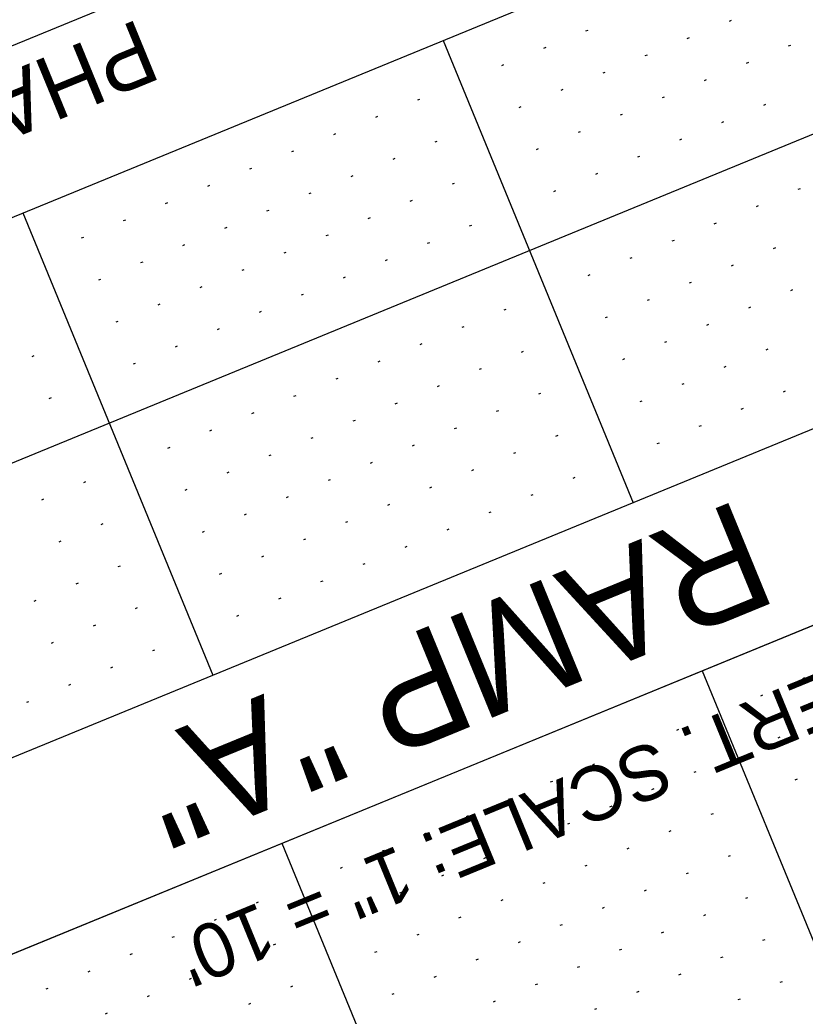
# Model space of a CAD drawing. Extents: x 2148770 to 2150891, y 142633 to 144465.
# Drawn here: x 2148940.4 to 2149026.8, y 143588.8 to 143698.4 of the extents above; entities that cross this region are included whole.
import ezdxf

# ---------------------------------------------------------------- set-up
doc = ezdxf.new("R2010")
doc.units = 0
for name, color, linetype in [('PR_Storm_Junction_Box', 7, 'Continuous'), ('SHT_Plan_Profile_Sheet_Txt', 7, 'Continuous'), ('SHT_Profile_Grid_Major', 7, 'Continuous'), ('SHT_Profile_Grid_Minor', 7, 'Continuous'), ('SHT_Scale', 7, 'Continuous'), ('SHT_Sheet_Border', 7, 'Continuous')]:
    doc.layers.add(name, color=color, linetype=linetype)

msp = doc.modelspace()

# ---------------------------------------------------------------- linework, layer by layer
at = {"layer": 'SHT_Profile_Grid_Major'}
for p, q in [((2150326.3, 144218.99), (2148869.31, 143620.81)), ((2150345.29, 144172.74), (2148888.3, 143574.55)), ((2148987.01, 143696.16), (2149007.9, 143645.28)), ((2148940.76, 143677.17), (2148961.65, 143626.29)), ((2149015.5, 143626.78), (2149167.42, 143256.75)), ((2148969.25, 143607.79), (2149121.17, 143237.76))]:
    msp.add_line(p, q, dxfattribs=at)
at = {"layer": 'SHT_Profile_Grid_Minor'}
for p, q in [((2149018.68, 143698.35), (2149018.45, 143698.25)), ((2149002.91, 143697.27), (2149002.67, 143697.18)), ((2149014.05, 143696.45), (2149013.82, 143696.35)), ((2148998.28, 143695.38), (2148998.05, 143695.28)), ((2149025.2, 143695.62), (2149024.97, 143695.53)), ((2149009.43, 143694.55), (2149009.2, 143694.45)), ((2148993.65, 143693.48), (2148993.42, 143693.38)), ((2149020.58, 143693.72), (2149020.35, 143693.63)), ((2149004.8, 143692.65), (2149004.57, 143692.55)), ((2149015.95, 143691.82), (2149015.72, 143691.73)), ((2149000.18, 143690.75), (2148999.95, 143690.66)), ((2149011.33, 143689.92), (2149011.1, 143689.83)), ((2148984.4, 143689.68), (2148984.17, 143689.58)), ((2148995.55, 143688.85), (2148995.32, 143688.76)), ((2149022.48, 143689.1), (2149022.25, 143689)), ((2148979.78, 143687.78), (2148979.55, 143687.68)), ((2149006.7, 143688.02), (2149006.47, 143687.93)), ((2149017.85, 143687.2), (2149017.62, 143687.1)), ((2148975.15, 143685.88), (2148974.92, 143685.79)), ((2149002.08, 143686.12), (2149001.85, 143686.03)), ((2148986.3, 143685.05), (2148986.07, 143684.96)), ((2149013.23, 143685.3), (2149013, 143685.2)), ((2148970.53, 143683.98), (2148970.3, 143683.89)), ((2148981.68, 143683.15), (2148981.45, 143683.06)), ((2148997.45, 143684.23), (2148997.22, 143684.13)), ((2149008.6, 143683.4), (2149008.37, 143683.3)), ((2148965.9, 143682.08), (2148965.67, 143681.99)), ((2148977.05, 143681.26), (2148976.82, 143681.16)), ((2149003.98, 143681.5), (2149003.75, 143681.4)), ((2148961.28, 143680.18), (2148961.05, 143680.09)), ((2148988.2, 143680.43), (2148987.97, 143680.33)), ((2148972.43, 143679.36), (2148972.2, 143679.26)), ((2148999.35, 143679.6), (2148999.12, 143679.51)), ((2149026.28, 143679.84), (2149026.04, 143679.75)), ((2148956.65, 143678.28), (2148956.42, 143678.19)), ((2148983.58, 143678.53), (2148983.34, 143678.43)), ((2149021.65, 143677.95), (2149021.42, 143677.85)), ((2148967.8, 143677.46), (2148967.57, 143677.36)), ((2148978.95, 143676.63), (2148978.72, 143676.53)), ((2148952.03, 143676.39), (2148951.79, 143676.29)), ((2148963.18, 143675.56), (2148962.94, 143675.46)), ((2148990.1, 143675.8), (2148989.87, 143675.71)), ((2149017.03, 143676.05), (2149016.79, 143675.95)), ((2148947.4, 143674.49), (2148947.17, 143674.39)), ((2148974.33, 143674.73), (2148974.09, 143674.64)), ((2148958.55, 143673.66), (2148958.32, 143673.56)), ((2148985.48, 143673.9), (2148985.24, 143673.81)), ((2149012.4, 143674.15), (2149012.17, 143674.05)), ((2149023.55, 143673.32), (2149023.32, 143673.23)), ((2148969.7, 143672.83), (2148969.47, 143672.74)), ((2149007.77, 143672.25), (2149007.54, 143672.15)), ((2148953.93, 143671.76), (2148953.69, 143671.67)), ((2148980.85, 143672), (2148980.62, 143671.91)), ((2149018.92, 143671.42), (2149018.69, 143671.33)), ((2148965.07, 143670.93), (2148964.84, 143670.84)), ((2148976.22, 143670.11), (2148975.99, 143670.01)), ((2149003.15, 143670.35), (2149002.92, 143670.25)), ((2148949.3, 143669.86), (2148949.07, 143669.77)), ((2148960.45, 143669.03), (2148960.22, 143668.94)), ((2149014.3, 143669.52), (2149014.07, 143669.43)), ((2148971.6, 143668.21), (2148971.37, 143668.11)), ((2149025.45, 143668.7), (2149025.22, 143668.6)), ((2148955.82, 143667.13), (2148955.59, 143667.04)), ((2149009.67, 143667.62), (2149009.44, 143667.53)), ((2149020.82, 143666.8), (2149020.59, 143666.7)), ((2148966.97, 143666.31), (2148966.74, 143666.21)), ((2148993.9, 143666.55), (2148993.67, 143666.46)), ((2149005.05, 143665.72), (2149004.82, 143665.63)), ((2148951.2, 143665.24), (2148950.97, 143665.14)), ((2148989.27, 143664.65), (2148989.04, 143664.56)), ((2149016.2, 143664.9), (2149015.97, 143664.8)), ((2148962.35, 143664.41), (2148962.12, 143664.31)), ((2148957.72, 143662.51), (2148957.49, 143662.41)), ((2148984.65, 143662.75), (2148984.42, 143662.66)), ((2149011.57, 143663), (2149011.34, 143662.9)), ((2148941.95, 143661.44), (2148941.72, 143661.34)), ((2148995.8, 143661.93), (2148995.57, 143661.83)), ((2149022.72, 143662.17), (2149022.49, 143662.08)), ((2148953.1, 143660.61), (2148952.87, 143660.52)), ((2148980.02, 143660.85), (2148979.79, 143660.76)), ((2149006.95, 143661.1), (2149006.72, 143661)), ((2149018.1, 143660.27), (2149017.87, 143660.18)), ((2148991.17, 143660.03), (2148990.94, 143659.93)), ((2148975.4, 143658.96), (2148975.17, 143658.86)), ((2148986.55, 143658.13), (2148986.32, 143658.03)), ((2149013.47, 143658.37), (2149013.24, 143658.28)), ((2148970.77, 143657.06), (2148970.54, 143656.96)), ((2148997.7, 143657.3), (2148997.47, 143657.21)), ((2149024.62, 143657.55), (2149024.39, 143657.45)), ((2148943.85, 143656.81), (2148943.62, 143656.72)), ((2148981.92, 143656.23), (2148981.69, 143656.13)), ((2149008.85, 143656.47), (2149008.62, 143656.38)), ((2148966.15, 143655.16), (2148965.92, 143655.06)), ((2148993.07, 143655.4), (2148992.84, 143655.31)), ((2149020, 143655.65), (2149019.76, 143655.55)), ((2148977.3, 143654.33), (2148977.07, 143654.24)), ((2149015.37, 143653.75), (2149015.14, 143653.65)), ((2148961.52, 143653.26), (2148961.29, 143653.16)), ((2148988.45, 143653.5), (2148988.21, 143653.41)), ((2148999.6, 143652.68), (2148999.36, 143652.58)), ((2148956.9, 143651.36), (2148956.66, 143651.26)), ((2148972.67, 143652.43), (2148972.44, 143652.34)), ((2148983.82, 143651.6), (2148983.59, 143651.51)), ((2149010.75, 143651.85), (2149010.51, 143651.75)), ((2148968.05, 143650.53), (2148967.81, 143650.44)), ((2148994.97, 143650.78), (2148994.74, 143650.68)), ((2148979.2, 143649.71), (2148978.96, 143649.61)), ((2148963.42, 143648.63), (2148963.19, 143648.54)), ((2148990.34, 143648.88), (2148990.11, 143648.78)), ((2148947.65, 143647.56), (2148947.41, 143647.47)), ((2148974.57, 143647.81), (2148974.34, 143647.71)), ((2148985.72, 143646.98), (2148985.49, 143646.88)), ((2149001.49, 143648.05), (2149001.26, 143647.96)), ((2148958.79, 143646.73), (2148958.56, 143646.64)), ((2148969.94, 143645.91), (2148969.71, 143645.81)), ((2148996.87, 143646.15), (2148996.64, 143646.06)), ((2148943.02, 143645.66), (2148942.79, 143645.57)), ((2148981.09, 143645.08), (2148980.86, 143644.98)), ((2148965.32, 143644.01), (2148965.09, 143643.91)), ((2148992.24, 143644.25), (2148992.01, 143644.16)), ((2148949.54, 143642.94), (2148949.31, 143642.84)), ((2148976.47, 143643.18), (2148976.24, 143643.09)), ((2148960.69, 143642.11), (2148960.46, 143642.01)), ((2148987.62, 143642.35), (2148987.39, 143642.26)), ((2148944.92, 143641.04), (2148944.69, 143640.94)), ((2148971.84, 143641.28), (2148971.61, 143641.19)), ((2148982.99, 143640.45), (2148982.76, 143640.36)), ((2148967.22, 143639.38), (2148966.99, 143639.29)), ((2148951.44, 143638.31), (2148951.21, 143638.22)), ((2148978.37, 143638.56), (2148978.14, 143638.46)), ((2148962.59, 143637.48), (2148962.36, 143637.39)), ((2148946.82, 143636.41), (2148946.59, 143636.32)), ((2148973.74, 143636.66), (2148973.51, 143636.56)), ((2148942.19, 143634.51), (2148941.96, 143634.42)), ((2148969.12, 143634.76), (2148968.89, 143634.66)), ((2148953.34, 143633.69), (2148953.11, 143633.59)), ((2148964.49, 143632.86), (2148964.26, 143632.76)), ((2148948.72, 143631.79), (2148948.49, 143631.69)), ((2148944.09, 143629.89), (2148943.86, 143629.79)), ((2148955.24, 143629.06), (2148955.01, 143628.97)), ((2148950.62, 143627.16), (2148950.38, 143627.07)), ((2148945.99, 143625.26), (2148945.76, 143625.17)), ((2149026.76, 143626), (2149026.53, 143625.9)), ((2149022.14, 143624.1), (2149021.91, 143624)), ((2148941.37, 143623.36), (2148941.13, 143623.27)), ((2149012.89, 143620.3), (2149012.66, 143620.2)), ((2149024.04, 143619.47), (2149023.81, 143619.38)), ((2149008.26, 143618.4), (2149008.03, 143618.3)), ((2149003.64, 143616.5), (2149003.41, 143616.41)), ((2149014.79, 143615.67), (2149014.56, 143615.58)), ((2148999.01, 143614.6), (2148998.78, 143614.51)), ((2149025.94, 143614.85), (2149025.71, 143614.75)), ((2149010.16, 143613.77), (2149009.93, 143613.68)), ((2148994.39, 143612.7), (2148994.16, 143612.61)), ((2149005.54, 143611.88), (2149005.31, 143611.78)), ((2148989.76, 143610.8), (2148989.53, 143610.71)), ((2149016.69, 143611.05), (2149016.46, 143610.95)), ((2149000.91, 143609.98), (2149000.68, 143609.88)), ((2148985.14, 143608.9), (2148984.91, 143608.81)), ((2149012.06, 143609.15), (2149011.83, 143609.05)), ((2148996.29, 143608.08), (2148996.06, 143607.98)), ((2148980.51, 143607.01), (2148980.28, 143606.91)), ((2149007.44, 143607.25), (2149007.2, 143607.15)), ((2149018.59, 143606.42), (2149018.35, 143606.33)), ((2148991.66, 143606.18), (2148991.43, 143606.08)), ((2149002.81, 143605.35), (2149002.58, 143605.26)), ((2148975.89, 143605.11), (2148975.65, 143605.01)), ((2148987.04, 143604.28), (2148986.8, 143604.18)), ((2149013.96, 143604.52), (2149013.73, 143604.43)), ((2148998.19, 143603.45), (2148997.95, 143603.36)), ((2148982.41, 143602.38), (2148982.18, 143602.29)), ((2149009.33, 143602.62), (2149009.1, 143602.53)), ((2148966.64, 143601.31), (2148966.4, 143601.21)), ((2148993.56, 143601.55), (2148993.33, 143601.46)), ((2149020.48, 143601.8), (2149020.25, 143601.7)), ((2148977.78, 143600.48), (2148977.55, 143600.39)), ((2149004.71, 143600.73), (2149004.48, 143600.63)), ((2149015.86, 143599.9), (2149015.63, 143599.8)), ((2148962.01, 143599.41), (2148961.78, 143599.31)), ((2148988.93, 143599.65), (2148988.7, 143599.56)), ((2149000.08, 143598.83), (2148999.85, 143598.73)), ((2148984.31, 143597.75), (2148984.08, 143597.66)), ((2149011.23, 143598), (2149011, 143597.9)), ((2148957.38, 143597.51), (2148957.15, 143597.42)), ((2148968.53, 143596.68), (2148968.3, 143596.59)), ((2148995.46, 143596.93), (2148995.23, 143596.83)), ((2149022.38, 143597.17), (2149022.15, 143597.08)), ((2148952.76, 143595.61), (2148952.53, 143595.52)), ((2148979.68, 143595.86), (2148979.45, 143595.76)), ((2149006.61, 143596.1), (2149006.38, 143596.01)), ((2148963.91, 143594.78), (2148963.68, 143594.69)), ((2148990.83, 143595.03), (2148990.6, 143594.93)), ((2149017.76, 143595.27), (2149017.53, 143595.18)), ((2148948.13, 143593.71), (2148947.9, 143593.62)), ((2149001.98, 143594.2), (2149001.75, 143594.11)), ((2149013.13, 143593.37), (2149012.9, 143593.28)), ((2148959.28, 143592.89), (2148959.05, 143592.79)), ((2148986.21, 143593.13), (2148985.98, 143593.03)), ((2148997.36, 143592.3), (2148997.13, 143592.21)), ((2149024.28, 143592.55), (2149024.05, 143592.45)), ((2148943.51, 143591.81), (2148943.28, 143591.72)), ((2148970.43, 143592.06), (2148970.2, 143591.96)), ((2148981.58, 143591.23), (2148981.35, 143591.14)), ((2149008.51, 143591.47), (2149008.28, 143591.38)), ((2148954.66, 143590.99), (2148954.43, 143590.89)), ((2148965.81, 143590.16), (2148965.58, 143590.06)), ((2148992.73, 143590.4), (2148992.5, 143590.31)), ((2149019.66, 143590.65), (2149019.43, 143590.55)), ((2148950.03, 143589.09), (2148949.8, 143588.99)), ((2149003.88, 143589.58), (2149003.65, 143589.48))]:
    msp.add_line(p, q, dxfattribs=at)
at = {"layer": 'SHT_Sheet_Border'}
for points in [[(2149079.81, 143753.17), (2149071.27, 143773.99), (2148846.94, 143681.89), (2148855.48, 143661.07)], [(2149061.75, 143645.77), (2149054.16, 143664.27), (2148915.4, 143607.3), (2148922.99, 143588.8)]]:
    msp.add_lwpolyline(points, close=True, dxfattribs=at)
msp.add_lwpolyline([(2149093.15, 143766.76), (2149102.65, 143743.63), (2148894.51, 143658.18)], dxfattribs=at)

# ---------------------------------------------------------------- texts
at = {"layer": 'PR_Storm_Junction_Box'}
msp.add_text('RAMP "A"', height=12, rotation=202.3213, dxfattribs=at).set_placement((2149019.59, 143645.75))
at = {"layer": 'SHT_Plan_Profile_Sheet_Txt'}
msp.add_text('PHASE 2', height=7, rotation=202.3213, dxfattribs=at).set_placement((2148953.54, 143698.6))
at = {"layer": 'SHT_Scale'}
msp.add_text('VERT. SCALE: 1" = 10\'', height=6, rotation=202.3213, dxfattribs=at).set_placement((2149034.41, 143629.14))

doc.saveas('drawing.dxf')
